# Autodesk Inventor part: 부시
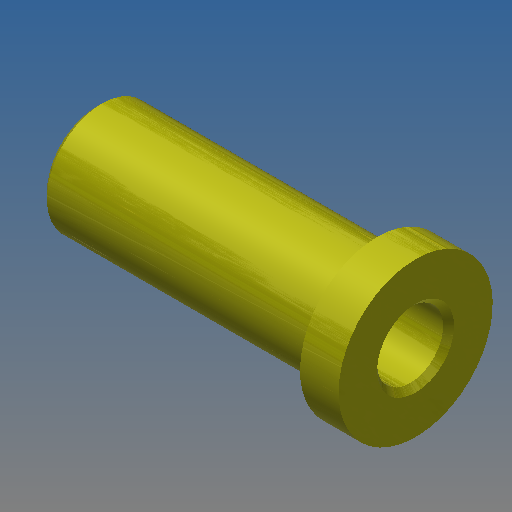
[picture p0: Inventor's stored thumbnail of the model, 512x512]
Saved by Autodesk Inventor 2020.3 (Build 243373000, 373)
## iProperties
Created: 2016-11
Part Number: 부시
Material: 강철, 연강
Document SubType Name: Modeling
Designer: mduedu
Density: 1 g/cm^3
Appearance: 노란색
Author: mduedu
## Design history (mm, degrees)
sketch "스케치1"
  geometry: L1 (0, 0)-(58, 0); L2 (58, 0)-(58, 14); L3 (58, 14)-(51, 14); L4 (51, 14)-(51, 10); L5 (51, 10)-(0, 10); L6 (0, 10)-(0, 0)
  constraints: 12 end point, 3 parallel, 2 perpendicular, 1 horizontal
  dimensions: "d0" = 58 distance of L1.start L1.end; "d1" = 7 distance of L2.end L3.end; "d2" = 28 diameter of L3 L1; "d3" = 20 diameter of L5 L1
revolve "회전1" sketch "스케치1" stored, may be unused: angle "d4" = 90 deg
hole "구멍1" diameter "d7" = 12; stored, may be unused: countersink angle "d11" = 90 deg, drill point angle "d13" = 118 deg; dims "d5" = 10, "d6" = 10, "d8" = 6, "d9" = 4, "d10" = 2, "d12" = 8
chamfer "모따기1" distance "d14" = 1; stored, may be unused: second distance "d15" = 2, angle "d16" = 45 deg
node "솔리드1"
